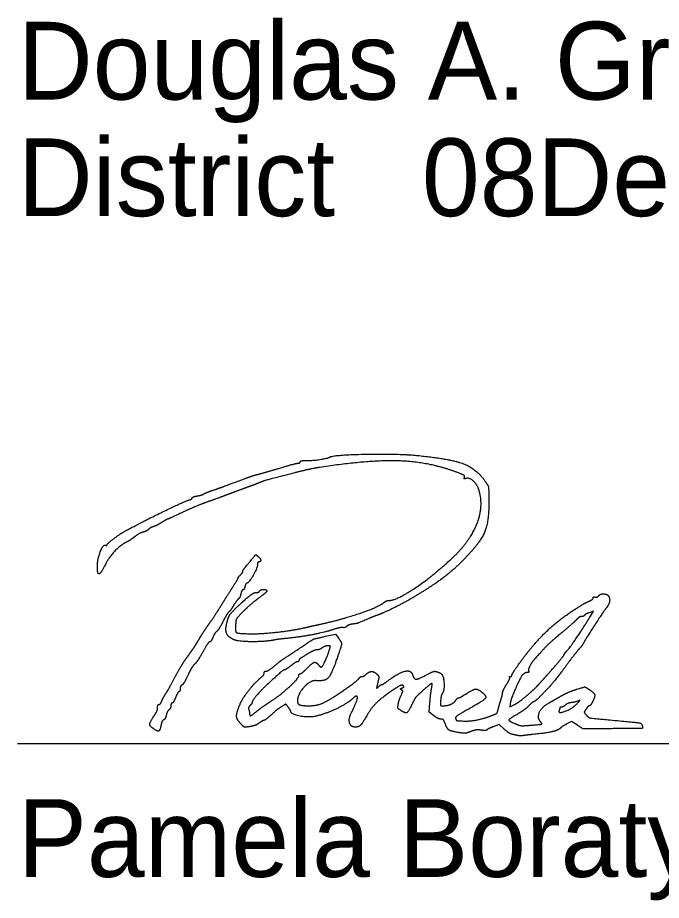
# Model space of a CAD drawing. Extents: x 0 to 34, y 0 to 22.
# Drawn here: x 24.2 to 25.36, y 1.019 to 2.609 of the extents above; entities that cross this region are included whole.
import ezdxf

# ---------------------------------------------------------------- set-up
doc = ezdxf.new("R2010")
doc.units = 0
for name, color, linetype in [('Default', 7, 'Continuous'), ('SH_Data', 7, 'Continuous'), ('SH_Text', 7, 'Continuous')]:
    doc.layers.add(name, color=color, linetype=linetype)

msp = doc.modelspace()

# ---------------------------------------------------------------- linework, layer by layer
at = {"layer": 'Default'}
for points in [[(25.2322, 1.531), (25.2376, 1.5399), (25.2302, 1.5373)], [(24.7549, 1.4948), (24.7729, 1.4989), (24.7776, 1.4927)], [(24.9498, 1.352), (24.9415, 1.3583), (24.943, 1.3754)], [(25.0878, 1.374), (25.0868, 1.3675), (25.0955, 1.372)], [(25.0768, 1.3277), (25.0676, 1.336), (25.0571, 1.3319)], [(25.2087, 1.3347), (25.198, 1.3415), (25.1896, 1.337)]]:
    msp.add_lwpolyline(points, dxfattribs=at)
for points in [[(24.7183, 1.8112), (24.7279, 1.8109), (24.7589, 1.8153), (24.7623, 1.8174)], [(24.7623, 1.8174), (24.7691, 1.8216), (24.8861, 1.8239), (24.9205, 1.8205)], [(24.9205, 1.8205), (24.9798, 1.8146), (25.0273, 1.7964), (25.0431, 1.7733)], [(24.6337, 1.7867), (24.639, 1.788), (24.6565, 1.793), (24.6725, 1.7978)], [(24.6725, 1.7978), (24.6886, 1.8026), (24.7035, 1.8065), (24.7055, 1.8065)], [(24.7441, 1.7989), (24.7349, 1.7975), (24.7149, 1.7932), (24.6997, 1.7892)], [(24.7055, 1.8065), (24.7076, 1.8065), (24.7093, 1.8076), (24.7093, 1.809)], [(24.7093, 1.809), (24.7093, 1.8103), (24.7133, 1.8113), (24.7183, 1.8112)], [(24.993, 1.7897), (24.9424, 1.8087), (24.8345, 1.8127), (24.7441, 1.7989)], [(24.6097, 1.7788), (24.6176, 1.7818), (24.6284, 1.7853), (24.6337, 1.7867)], [(24.6997, 1.7892), (24.6487, 1.7761), (24.6444, 1.7748), (24.6337, 1.7705)], [(25.0053, 1.7811), (25.0063, 1.7836), (25.0028, 1.786), (24.993, 1.7897)], [(25.0077, 1.779), (25.0051, 1.778), (25.0044, 1.7787), (25.0053, 1.7811)], [(24.5533, 1.7582), (24.568, 1.7633), (24.5745, 1.7657), (24.6097, 1.7788)], [(24.6337, 1.7705), (24.6311, 1.7694), (24.6208, 1.7656), (24.6109, 1.762)], [(25.0311, 1.7591), (25.0278, 1.7689), (25.0134, 1.7812), (25.0077, 1.779)], [(25.0431, 1.7733), (25.048, 1.7661), (25.049, 1.7617), (25.0493, 1.7439)], [(24.5239, 1.7476), (24.5288, 1.7485), (24.534, 1.7501), (24.5353, 1.7511)], [(24.5353, 1.7511), (24.5366, 1.752), (24.5447, 1.7553), (24.5533, 1.7582)], [(24.5773, 1.7496), (24.5687, 1.7463), (24.5525, 1.7404), (24.5413, 1.7364)], [(24.6109, 1.762), (24.601, 1.7584), (24.5859, 1.7528), (24.5773, 1.7496)], [(24.9856, 1.6379), (25.0165, 1.6674), (25.0404, 1.7309), (25.0311, 1.7591)], [(24.3973, 1.6861), (24.4275, 1.7023), (24.5011, 1.738), (24.5095, 1.7404)], [(24.5413, 1.7364), (24.5301, 1.7325), (24.5097, 1.7239), (24.4961, 1.7174)], [(24.5095, 1.7404), (24.5125, 1.7413), (24.5149, 1.7429), (24.5149, 1.744)], [(24.5149, 1.744), (24.5149, 1.745), (24.5189, 1.7467), (24.5239, 1.7476)], [(25.0493, 1.7439), (25.05, 1.7031), (25.0339, 1.6634), (25.0045, 1.6335)], [(24.4961, 1.7174), (24.4824, 1.711), (24.4708, 1.7057), (24.4702, 1.7057)], [(24.4702, 1.7057), (24.4697, 1.7057), (24.4652, 1.7031), (24.4602, 1.7)], [(24.3613, 1.6594), (24.3613, 1.6616), (24.3867, 1.6804), (24.3973, 1.6861)], [(24.4362, 1.6873), (24.4344, 1.6855), (24.4301, 1.6834), (24.4265, 1.6825)], [(24.4454, 1.6925), (24.4422, 1.6915), (24.438, 1.6891), (24.4362, 1.6873)], [(24.4602, 1.7), (24.4553, 1.6969), (24.4486, 1.6935), (24.4454, 1.6925)], [(24.4117, 1.6744), (24.4071, 1.6708), (24.3999, 1.6662), (24.3958, 1.6641)], [(24.4265, 1.6825), (24.423, 1.6816), (24.4163, 1.678), (24.4117, 1.6744)], [(24.3441, 1.6216), (24.3442, 1.6348), (24.3549, 1.6614), (24.359, 1.6588)], [(24.359, 1.6588), (24.3603, 1.658), (24.3613, 1.6583), (24.3613, 1.6594)], [(24.3958, 1.6641), (24.3854, 1.6588), (24.3655, 1.6379), (24.3593, 1.6258)], [(24.6115, 1.6205), (24.63, 1.6426), (24.6293, 1.6421), (24.6334, 1.6387)], [(24.6334, 1.6387), (24.6377, 1.6351), (24.6386, 1.6289), (24.6349, 1.6289)], [(24.8689, 1.5593), (24.883, 1.5593), (24.9511, 1.6052), (24.9856, 1.6379)], [(24.3455, 1.6079), (24.3447, 1.6087), (24.3441, 1.6148), (24.3441, 1.6216)], [(24.3593, 1.6258), (24.3526, 1.6129), (24.3473, 1.606), (24.3455, 1.6079)], [(24.6325, 1.6238), (24.6325, 1.6182), (24.6166, 1.5905), (24.6134, 1.5905)], [(24.6349, 1.6289), (24.6336, 1.6289), (24.6325, 1.6266), (24.6325, 1.6238)], [(25.0045, 1.6335), (24.9859, 1.6146), (24.9535, 1.5897), (24.923, 1.5709)], [(24.6013, 1.6049), (24.6039, 1.6075), (24.6061, 1.6106), (24.6061, 1.6119)], [(24.6061, 1.6119), (24.6061, 1.6131), (24.6085, 1.617), (24.6115, 1.6205)], [(24.5885, 1.5844), (24.5941, 1.593), (24.5981, 1.6001), (24.5975, 1.6001)], [(24.5975, 1.6001), (24.597, 1.6001), (24.5987, 1.6022), (24.6013, 1.6049)], [(24.6134, 1.5905), (24.6123, 1.5905), (24.6107, 1.5878), (24.6099, 1.5845)], [(24.5665, 1.5494), (24.5731, 1.56), (24.583, 1.5758), (24.5885, 1.5844)], [(24.6062, 1.5785), (24.605, 1.5785), (24.6034, 1.5752), (24.6025, 1.5713)], [(24.6099, 1.5845), (24.6091, 1.5812), (24.6074, 1.5785), (24.6062, 1.5785)], [(24.6301, 1.5737), (24.6326, 1.5737), (24.6353, 1.5747), (24.6361, 1.5761)], [(24.6493, 1.5764), (24.6493, 1.5753), (24.6425, 1.5694), (24.6343, 1.5633)], [(24.6361, 1.5761), (24.6379, 1.579), (24.6493, 1.5793), (24.6493, 1.5764)], [(24.5986, 1.5627), (24.5973, 1.5619), (24.5935, 1.5568), (24.5901, 1.5513)], [(24.5977, 1.5495), (24.6134, 1.5641), (24.6262, 1.5737), (24.6301, 1.5737)], [(24.6025, 1.5713), (24.6016, 1.5673), (24.5999, 1.5635), (24.5986, 1.5627)], [(24.6343, 1.5633), (24.626, 1.5572), (24.6135, 1.5463), (24.6065, 1.5392)], [(24.923, 1.5709), (24.9039, 1.559), (24.8626, 1.538), (24.8485, 1.5329)], [(24.8607, 1.5559), (24.8628, 1.5578), (24.8665, 1.5593), (24.8689, 1.5593)], [(25.2005, 1.5409), (25.2195, 1.5531), (25.2213, 1.5542), (25.2295, 1.5579)], [(25.2295, 1.5579), (25.2338, 1.5598), (25.2373, 1.5627), (25.2373, 1.5642)], [(25.2373, 1.5642), (25.2373, 1.5657), (25.2388, 1.5664), (25.2407, 1.5657)], [(25.2407, 1.5657), (25.2426, 1.5649), (25.2454, 1.5659), (25.247, 1.5678)], [(25.247, 1.5678), (25.2486, 1.5697), (25.2523, 1.5713), (25.2552, 1.5713)], [(25.2552, 1.5713), (25.2647, 1.5713), (25.2684, 1.5552), (25.261, 1.5462)], [(24.5447, 1.5164), (24.5501, 1.5239), (24.5599, 1.5387), (24.5665, 1.5494)], [(24.5764, 1.5149), (24.5791, 1.5279), (24.5853, 1.5379), (24.5977, 1.5495)], [(24.5901, 1.5513), (24.5867, 1.5458), (24.5826, 1.5402), (24.581, 1.5388)], [(24.7489, 1.5173), (24.7858, 1.5255), (24.8521, 1.5484), (24.8607, 1.5559)], [(25.261, 1.5462), (25.2568, 1.5412), (25.224, 1.4908), (25.2208, 1.4846)], [(24.581, 1.5388), (24.5793, 1.5375), (24.5746, 1.5299), (24.5706, 1.5219)], [(24.6065, 1.5392), (24.5958, 1.5282), (24.5936, 1.5246), (24.5931, 1.5163)], [(24.8329, 1.5267), (24.8158, 1.5193), (24.8109, 1.5176), (24.8043, 1.5168)], [(24.8485, 1.5329), (24.8439, 1.5313), (24.8368, 1.5285), (24.8329, 1.5267)], [(25.1059, 1.4484), (25.1282, 1.4792), (25.1732, 1.5232), (25.2005, 1.5409)], [(25.1894, 1.4681), (25.1922, 1.47), (25.2204, 1.5115), (25.2322, 1.531)], [(25.2162, 1.5305), (25.214, 1.5305), (25.2101, 1.528), (25.2074, 1.5251)], [(25.2215, 1.5326), (25.2208, 1.5314), (25.2184, 1.5305), (25.2162, 1.5305)], [(25.2302, 1.5373), (25.2262, 1.5359), (25.2223, 1.5338), (25.2215, 1.5326)], [(24.528, 1.4909), (24.5319, 1.4975), (24.5394, 1.509), (24.5447, 1.5164)], [(24.5706, 1.5219), (24.5666, 1.5139), (24.5615, 1.5059), (24.5594, 1.5041)], [(24.5917, 1.488), (24.5813, 1.4919), (24.5741, 1.5044), (24.5764, 1.5149)], [(24.5931, 1.5163), (24.5922, 1.5029), (24.5963, 1.5), (24.6169, 1.4994)], [(24.7153, 1.5098), (24.7232, 1.5116), (24.7383, 1.515), (24.7489, 1.5173)], [(24.7867, 1.5106), (24.785, 1.5112), (24.7769, 1.5095), (24.7687, 1.5069)], [(24.7935, 1.5128), (24.7914, 1.511), (24.7883, 1.51), (24.7867, 1.5106)], [(24.8043, 1.5168), (24.8004, 1.5164), (24.7956, 1.5146), (24.7935, 1.5128)], [(25.2074, 1.5251), (25.2047, 1.5221), (25.1922, 1.511), (25.1797, 1.5005)], [(24.5594, 1.5041), (24.5572, 1.5023), (24.5539, 1.4972), (24.5521, 1.4928)], [(24.6169, 1.4994), (24.6361, 1.4989), (24.694, 1.505), (24.7153, 1.5098)], [(24.7687, 1.5069), (24.7522, 1.5016), (24.7071, 1.4931), (24.6833, 1.4908)], [(24.7009, 1.4684), (24.7326, 1.4894), (24.7339, 1.4901), (24.7549, 1.4948)], [(25.1797, 1.5005), (25.1601, 1.484), (25.1484, 1.4726), (25.1317, 1.4537)], [(24.515, 1.4702), (24.5183, 1.475), (24.5242, 1.4843), (24.528, 1.4909)], [(24.5464, 1.4849), (24.5451, 1.4849), (24.5397, 1.477), (24.5343, 1.4673)], [(24.5521, 1.4928), (24.5502, 1.4885), (24.5477, 1.4849), (24.5464, 1.4849)], [(24.6629, 1.4882), (24.6492, 1.4851), (24.5997, 1.485), (24.5917, 1.488)], [(24.6833, 1.4908), (24.675, 1.49), (24.6658, 1.4888), (24.6629, 1.4882)], [(24.7776, 1.4927), (24.7842, 1.4839), (24.784, 1.4791), (24.7763, 1.4565)], [(25.2208, 1.4846), (25.2191, 1.4811), (25.2152, 1.4757), (25.2122, 1.4725)], [(24.5014, 1.451), (24.5055, 1.4568), (24.5116, 1.4655), (24.515, 1.4702)], [(24.5343, 1.4673), (24.529, 1.4576), (24.5223, 1.4476), (24.5195, 1.4451)], [(24.6617, 1.4405), (24.6754, 1.4515), (24.6734, 1.4502), (24.7009, 1.4684)], [(24.7306, 1.4673), (24.7162, 1.4594), (24.7069, 1.453), (24.7069, 1.451)], [(24.7403, 1.4705), (24.7381, 1.4705), (24.7337, 1.469), (24.7306, 1.4673)], [(24.749, 1.474), (24.7465, 1.472), (24.7425, 1.4705), (24.7403, 1.4705)], [(24.7475, 1.4393), (24.7493, 1.4393), (24.7591, 1.4604), (24.7622, 1.4711)], [(24.7589, 1.4776), (24.756, 1.4775), (24.7516, 1.4759), (24.749, 1.474)], [(24.7622, 1.4711), (24.7639, 1.4768), (24.7635, 1.4776), (24.7589, 1.4776)], [(25.1542, 1.4251), (25.1695, 1.4422), (25.1831, 1.4586), (25.1855, 1.4629)], [(25.1855, 1.4629), (25.1867, 1.4651), (25.1885, 1.4674), (25.1894, 1.4681)], [(25.2122, 1.4725), (25.2092, 1.4692), (25.2003, 1.4579), (25.1924, 1.4472)], [(24.4825, 1.4189), (24.4888, 1.4307), (24.4973, 1.4452), (24.5014, 1.451)], [(24.7042, 1.4489), (24.7028, 1.4489), (24.6975, 1.4456), (24.6925, 1.4417)], [(24.7069, 1.451), (24.7069, 1.4498), (24.7057, 1.4489), (24.7042, 1.4489)], [(24.7213, 1.4369), (24.7314, 1.447), (24.738, 1.4488), (24.7429, 1.4429)], [(24.7763, 1.4565), (24.766, 1.4266), (24.7541, 1.4135), (24.7381, 1.4149)], [(25.0909, 1.425), (25.0909, 1.4264), (25.0976, 1.4369), (25.1059, 1.4484)], [(25.1317, 1.4537), (25.1259, 1.4471), (25.1196, 1.4342), (25.121, 1.4318)], [(25.1924, 1.4472), (25.1845, 1.4366), (25.1769, 1.4264), (25.1754, 1.4246)], [(24.5195, 1.4451), (24.5166, 1.4425), (24.5111, 1.4334), (24.5072, 1.4249)], [(24.6445, 1.4286), (24.6445, 1.4305), (24.646, 1.4321), (24.6479, 1.4321)], [(24.6813, 1.4344), (24.6795, 1.4344), (24.671, 1.4272), (24.6457, 1.4039)], [(24.6479, 1.4321), (24.6497, 1.4321), (24.6559, 1.4358), (24.6617, 1.4405)], [(24.6925, 1.4417), (24.6875, 1.4377), (24.6825, 1.4345), (24.6813, 1.4344)], [(24.7093, 1.4273), (24.7106, 1.4273), (24.716, 1.4316), (24.7213, 1.4369)], [(24.7429, 1.4429), (24.7445, 1.4409), (24.7466, 1.4393), (24.7475, 1.4393)], [(24.8281, 1.4264), (24.833, 1.4313), (24.843, 1.4314), (24.8479, 1.4264)], [(24.8661, 1.4138), (24.8863, 1.429), (24.909, 1.4346), (24.912, 1.4251)], [(24.9358, 1.4248), (24.9477, 1.4314), (24.955, 1.4321), (24.9632, 1.4275)], [(25.121, 1.4318), (25.1218, 1.4306), (25.1207, 1.4297), (25.1188, 1.4297)], [(24.4671, 1.3913), (24.4693, 1.3946), (24.4763, 1.407), (24.4825, 1.4189)], [(24.5072, 1.4249), (24.5032, 1.4163), (24.4985, 1.4084), (24.4967, 1.4073)], [(24.601, 1.3726), (24.6055, 1.383), (24.6287, 1.4125), (24.6391, 1.4208)], [(24.6391, 1.4208), (24.6421, 1.4232), (24.6445, 1.4267), (24.6445, 1.4286)], [(24.6608, 1.3807), (24.6764, 1.3911), (24.7069, 1.4198), (24.7069, 1.4241)], [(24.7381, 1.4149), (24.7277, 1.4158), (24.7045, 1.3904), (24.7045, 1.3781)], [(24.7069, 1.4241), (24.7069, 1.4258), (24.708, 1.4273), (24.7093, 1.4273)], [(24.7729, 1.3876), (24.7915, 1.3999), (24.8139, 1.4166), (24.8156, 1.4194)], [(24.8156, 1.4194), (24.8167, 1.4211), (24.819, 1.4225), (24.8208, 1.4225)], [(24.8208, 1.4225), (24.8227, 1.4225), (24.8259, 1.4242), (24.8281, 1.4264)], [(24.8479, 1.4264), (24.8511, 1.4233), (24.8513, 1.4208), (24.8492, 1.4117)], [(24.912, 1.4251), (24.9144, 1.4175), (24.9225, 1.4174), (24.9358, 1.4248)], [(24.9632, 1.4275), (24.9676, 1.425), (24.9693, 1.397), (24.9654, 1.3919)], [(25.0811, 1.4082), (25.085, 1.4144), (25.0875, 1.4202), (25.0867, 1.421)], [(25.0867, 1.421), (25.0859, 1.4218), (25.0866, 1.4225), (25.0881, 1.4225)], [(25.0881, 1.4225), (25.0896, 1.4225), (25.0909, 1.4236), (25.0909, 1.425)], [(25.1188, 1.4297), (25.1124, 1.4297), (25.1029, 1.4145), (25.0908, 1.3853)], [(25.1386, 1.4076), (25.1417, 1.4112), (25.1488, 1.419), (25.1542, 1.4251)], [(25.1754, 1.4246), (25.1621, 1.4081), (25.1576, 1.403), (25.1457, 1.3908)], [(24.4933, 1.4009), (24.4933, 1.3984), (24.4922, 1.3956), (24.4908, 1.3948)], [(24.4967, 1.4073), (24.4948, 1.4063), (24.4933, 1.4034), (24.4933, 1.4009)], [(24.6457, 1.4039), (24.6366, 1.3955), (24.6229, 1.3785), (24.6229, 1.3755)], [(24.8492, 1.4117), (24.8469, 1.4014), (24.847, 1.4009), (24.8508, 1.4044)], [(24.8508, 1.4044), (24.853, 1.4064), (24.8557, 1.4081), (24.8566, 1.4081)], [(24.8566, 1.4081), (24.8576, 1.4081), (24.8619, 1.4106), (24.8661, 1.4138)], [(24.8947, 1.406), (24.8929, 1.4078), (24.887, 1.405), (24.8745, 1.3965)], [(24.8919, 1.3983), (24.8897, 1.3997), (24.89, 1.4006), (24.8931, 1.4018)], [(24.8931, 1.4018), (24.8961, 1.4029), (24.8966, 1.4042), (24.8947, 1.406)], [(24.9358, 1.4019), (24.9199, 1.3879), (24.9162, 1.3835), (24.9107, 1.3721)], [(24.9459, 1.4003), (24.9478, 1.4097), (24.9451, 1.4101), (24.9358, 1.4019)], [(24.943, 1.3754), (24.9438, 1.3848), (24.9451, 1.396), (24.9459, 1.4003)], [(25.0085, 1.3913), (25.0214, 1.3995), (25.029, 1.4003), (25.0367, 1.3942)], [(25.0741, 1.3934), (25.0741, 1.3952), (25.0773, 1.4019), (25.0811, 1.4082)], [(25.1185, 1.3888), (25.1264, 1.3956), (25.1355, 1.4041), (25.1386, 1.4076)], [(25.1785, 1.3868), (25.1864, 1.3913), (25.1996, 1.397), (25.2078, 1.3995)], [(25.2078, 1.3995), (25.2218, 1.4037), (25.223, 1.4037), (25.2289, 1.3999)], [(25.2289, 1.3999), (25.2385, 1.3936), (25.2409, 1.3862), (25.2363, 1.3772)], [(24.4602, 1.3787), (24.4618, 1.3823), (24.4649, 1.388), (24.4671, 1.3913)], [(24.4845, 1.3839), (24.4825, 1.3787), (24.4798, 1.3745), (24.4786, 1.3745)], [(24.4908, 1.3948), (24.4894, 1.3939), (24.4866, 1.389), (24.4845, 1.3839)], [(24.7244, 1.3697), (24.7375, 1.3697), (24.7566, 1.3767), (24.7729, 1.3876)], [(24.8049, 1.3834), (24.7953, 1.3743), (24.7566, 1.3555), (24.7381, 1.351)], [(24.8019, 1.3577), (24.806, 1.3653), (24.8125, 1.3816), (24.8125, 1.3843)], [(24.8125, 1.3843), (24.8125, 1.3874), (24.8085, 1.3869), (24.8049, 1.3834)], [(24.8745, 1.3965), (24.8548, 1.3831), (24.8376, 1.366), (24.8293, 1.3517)], [(24.8861, 1.3729), (24.8869, 1.377), (24.8892, 1.3841), (24.8912, 1.3885)], [(24.8912, 1.3885), (24.8941, 1.3948), (24.8942, 1.3969), (24.8919, 1.3983)], [(24.9654, 1.3919), (24.9641, 1.3902), (24.9628, 1.3845), (24.9624, 1.3793)], [(24.9894, 1.3792), (24.9912, 1.3819), (24.9937, 1.3841), (24.9949, 1.3841)], [(24.9949, 1.3841), (24.9961, 1.3841), (25.0022, 1.3873), (25.0085, 1.3913)], [(25.0367, 1.3942), (25.0464, 1.3866), (25.0395, 1.3787), (25.008, 1.361)], [(25.0706, 1.3793), (25.0725, 1.3852), (25.0741, 1.3916), (25.0741, 1.3934)], [(25.0908, 1.3853), (25.0897, 1.3826), (25.0884, 1.3775), (25.0878, 1.374)], [(25.0955, 1.372), (25.1002, 1.3744), (25.1106, 1.382), (25.1185, 1.3888)], [(25.1457, 1.3908), (25.1382, 1.3831), (25.1312, 1.3769), (25.1301, 1.3769)], [(25.1589, 1.3758), (25.1618, 1.3773), (25.1706, 1.3823), (25.1785, 1.3868)], [(24.4525, 1.3664), (24.4525, 1.3695), (24.4536, 1.3721), (24.4549, 1.3721)], [(24.4549, 1.3721), (24.4563, 1.3721), (24.4587, 1.375), (24.4602, 1.3787)], [(24.4765, 1.37), (24.4765, 1.3675), (24.4749, 1.3642), (24.473, 1.3626)], [(24.4786, 1.3745), (24.4775, 1.3745), (24.4765, 1.3724), (24.4765, 1.37)], [(24.6027, 1.3369), (24.5951, 1.3445), (24.5945, 1.3573), (24.601, 1.3726)], [(24.6192, 1.3704), (24.6171, 1.3683), (24.616, 1.3651), (24.6168, 1.3632)], [(24.6229, 1.3755), (24.6229, 1.3747), (24.6212, 1.3724), (24.6192, 1.3704)], [(24.6293, 1.3583), (24.6368, 1.3644), (24.6421, 1.3682), (24.6608, 1.3807)], [(24.6766, 1.3685), (24.6684, 1.3631), (24.6658, 1.3611), (24.6546, 1.3511)], [(24.6879, 1.3671), (24.6834, 1.3729), (24.6834, 1.3729), (24.6766, 1.3685)], [(24.7045, 1.3781), (24.7045, 1.373), (24.7123, 1.3697), (24.7244, 1.3697)], [(24.8907, 1.3613), (24.8857, 1.3646), (24.8849, 1.3666), (24.8861, 1.3729)], [(24.9107, 1.3721), (24.904, 1.3584), (24.8992, 1.3558), (24.8907, 1.3613)], [(24.9624, 1.3793), (24.9619, 1.3717), (24.9626, 1.3697), (24.9658, 1.3697)], [(24.9658, 1.3697), (24.9741, 1.3697), (24.9861, 1.3745), (24.9894, 1.3792)], [(25.0658, 1.3622), (25.0665, 1.3656), (25.0687, 1.3733), (25.0706, 1.3793)], [(25.1215, 1.3699), (25.1179, 1.3661), (25.1098, 1.36), (25.1035, 1.3563)], [(25.1301, 1.3769), (25.129, 1.3769), (25.1251, 1.3737), (25.1215, 1.3699)], [(25.1419, 1.3414), (25.1358, 1.3488), (25.1456, 1.3686), (25.1589, 1.3758)], [(25.1759, 1.3615), (25.1734, 1.355), (25.1988, 1.364), (25.2073, 1.3726)], [(25.1801, 1.3673), (25.1786, 1.3673), (25.1773, 1.3668), (25.1773, 1.3663)], [(25.1869, 1.3709), (25.1847, 1.3689), (25.1817, 1.3673), (25.1801, 1.3673)], [(25.1979, 1.3754), (25.194, 1.3749), (25.1891, 1.3728), (25.1869, 1.3709)], [(25.2097, 1.3781), (25.2071, 1.3771), (25.2017, 1.3759), (25.1979, 1.3754)], [(25.2073, 1.3726), (25.2128, 1.3782), (25.2134, 1.3795), (25.2097, 1.3781)], [(25.2303, 1.3697), (25.2292, 1.3697), (25.2265, 1.367), (25.2244, 1.3638)], [(25.2363, 1.3772), (25.2341, 1.373), (25.2314, 1.3697), (25.2303, 1.3697)], [(24.445, 1.3285), (24.438, 1.3333), (24.4385, 1.34), (24.4467, 1.3522)], [(24.4467, 1.3522), (24.4499, 1.3569), (24.4525, 1.3633), (24.4525, 1.3664)], [(24.468, 1.3525), (24.4672, 1.3486), (24.465, 1.3448), (24.4633, 1.3441)], [(24.473, 1.3626), (24.4712, 1.361), (24.4689, 1.3565), (24.468, 1.3525)], [(24.6168, 1.3632), (24.6175, 1.3612), (24.6181, 1.3581), (24.6181, 1.3563)], [(24.6181, 1.3563), (24.6181, 1.3514), (24.6215, 1.352), (24.6293, 1.3583)], [(24.6924, 1.3597), (24.6924, 1.3606), (24.6904, 1.3639), (24.6879, 1.3671)], [(24.7381, 1.351), (24.7252, 1.348), (24.6926, 1.3541), (24.6924, 1.3597)], [(24.8086, 1.3313), (24.8002, 1.3313), (24.7962, 1.3471), (24.8019, 1.3577)], [(24.8293, 1.3517), (24.8211, 1.3375), (24.8147, 1.3313), (24.8086, 1.3313)], [(24.9628, 1.3457), (24.9603, 1.3457), (24.9544, 1.3485), (24.9498, 1.352)], [(25.008, 1.361), (24.9947, 1.3535), (24.9885, 1.3487), (24.9893, 1.3465)], [(25.0033, 1.3422), (25.0138, 1.3416), (25.04, 1.3465), (25.0531, 1.3516)], [(25.0531, 1.3516), (25.0619, 1.3549), (25.0649, 1.3574), (25.0658, 1.3622)], [(25.1035, 1.3563), (25.0856, 1.3459), (25.0846, 1.3426), (25.0975, 1.3371)], [(25.1773, 1.3663), (25.1773, 1.3657), (25.1766, 1.3636), (25.1759, 1.3615)], [(25.2244, 1.3638), (25.2209, 1.3585), (25.221, 1.3576), (25.2248, 1.3529)], [(25.2248, 1.3529), (25.2284, 1.3484), (25.2334, 1.3474), (25.2673, 1.3442)], [(24.4633, 1.3441), (24.4616, 1.3435), (24.4595, 1.3393), (24.4587, 1.3349)], [(24.6189, 1.3322), (24.6102, 1.3309), (24.608, 1.3315), (24.6027, 1.3369)], [(24.6354, 1.3385), (24.6318, 1.3359), (24.6244, 1.3331), (24.6189, 1.3322)], [(24.6439, 1.3433), (24.6428, 1.3433), (24.639, 1.3411), (24.6354, 1.3385)], [(24.6546, 1.3511), (24.6498, 1.3468), (24.645, 1.3433), (24.6439, 1.3433)], [(24.9704, 1.3379), (24.9685, 1.343), (24.966, 1.3457), (24.9628, 1.3457)], [(24.9957, 1.3213), (24.9807, 1.3237), (24.9739, 1.3282), (24.9704, 1.3379)], [(24.9893, 1.3465), (24.9907, 1.3431), (24.9914, 1.3429), (25.0033, 1.3422)], [(25.0975, 1.3371), (25.1043, 1.3341), (25.1108, 1.3336), (25.1243, 1.3346)], [(25.1243, 1.3346), (25.1438, 1.3362), (25.1456, 1.3369), (25.1419, 1.3414)], [(25.1896, 1.337), (25.185, 1.3345), (25.1797, 1.331), (25.1779, 1.3291)], [(25.2673, 1.3442), (25.3164, 1.3397), (25.3247, 1.3381), (25.3256, 1.3334)], [(24.4587, 1.3349), (24.4568, 1.3252), (24.4526, 1.3232), (24.445, 1.3285)], [(25.0168, 1.3233), (25.0098, 1.3205), (25.0043, 1.32), (24.9957, 1.3213)], [(25.0357, 1.3258), (25.0299, 1.3266), (25.0226, 1.3256), (25.0168, 1.3233)], [(25.0458, 1.3262), (25.0454, 1.3253), (25.0408, 1.3251), (25.0357, 1.3258)], [(25.0571, 1.3319), (25.0512, 1.3296), (25.0462, 1.3271), (25.0458, 1.3262)], [(25.0914, 1.3182), (25.0884, 1.3189), (25.0818, 1.3231), (25.0768, 1.3277)], [(25.1779, 1.3291), (25.1742, 1.3254), (25.1527, 1.3205), (25.1293, 1.3181)], [(25.2553, 1.3283), (25.2196, 1.3279), (25.2192, 1.3279), (25.2087, 1.3347)], [(25.3256, 1.3334), (25.3264, 1.3291), (25.3244, 1.329), (25.2553, 1.3283)], [(25.1017, 1.3161), (25.0991, 1.3166), (25.0944, 1.3176), (25.0914, 1.3182)], [(25.1101, 1.3158), (25.1081, 1.3154), (25.1043, 1.3155), (25.1017, 1.3161)], [(25.1293, 1.3181), (25.1207, 1.3172), (25.1121, 1.3162), (25.1101, 1.3158)]]:
    msp.add_open_spline(points, degree=2, dxfattribs=at)
at = {"layer": 'SH_Data'}
for p, q in [((24.2004, 1.8015), (24.2004, 1.8015)), ((24.2004, 1.3015), (27.7004, 1.3015))]:
    msp.add_line(p, q, dxfattribs=at)

# ---------------------------------------------------------------- texts
at = {"layer": 'SH_Text'}
for s, p in [('Douglas A. Gruver, P.E.', (24.2004, 2.4615)), ('District       Deputy Director', (24.2004, 2.2515)), ('              08', (24.2004, 2.2515)), ('Pamela Boratyn', (24.2004, 1.0615))]:
    msp.add_text(s, height=0.14, dxfattribs=at).set_placement(p)

doc.saveas('drawing.dxf')
